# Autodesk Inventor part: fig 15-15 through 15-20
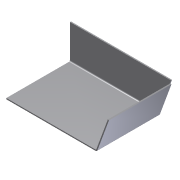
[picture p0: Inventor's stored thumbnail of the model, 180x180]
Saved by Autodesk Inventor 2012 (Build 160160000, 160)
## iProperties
Created: 2005-03
Part Number: fig 15-15 through 15-20
Document SubType Name: Sheet Metal
Designer: CADCIM
Manufacturer: Standard
Standards Organization: Custom
Density: 1 g/cm^3
Sheet Metal Rule: Default
Material: Default
Author: CADCIM
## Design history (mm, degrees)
node "Face2"
  sketch "Sketch1" dims "d32" = 0.5 (= BendRadius)
    geometry: L1 (-36, -8.631)-(4.238, -8.631); L2 (4.238, -8.631)-(4.238, 20); L3 (4.238, 20)-(-36, 20); L4 (-36, 20)-(-36, -8.631)
    constraints: 8 end point, 2 parallel, 1 horizontal, 1 perpendicular
node "Flange3"
node "Flange2"
feature "Corner2" dims "d36" = 2 (= CornerReliefSize), "d37" = 0.5 (= BendRadius), "d38" = 0.5 (= Thickness), "d39" = 0, "Thickness" = 0.5
body "Solid1"
face "Plate2" dims "Thickness" = 0.5
sketch "Sketch3" dims "CornerReliefSize" = 2 (= 4 x Thickness)
  geometry: L1 (39.356, 0)-(39.356, 15); L2 (39.356, 15)-(0, 15); 2 other entities
  constraints: 4 end point, 4 other
face "Plate4" dims "d18" = 0.5 (= BendReliefWidth), "d20" = 1 (= MinimumRemnant), "d22" = 15, "d23" = 90 deg, "d24" = 0.5 (= BendRadius), "d32" = 0.5 (= BendRadius), "Thickness" = 0.5, "CornerReliefSize" = 2 (= 4 x Thickness)
bend "Bend2" dims "d18" = 0.5 (= BendReliefWidth), "d19" = 0.25 (= BendReliefDepth), "d20" = 1 (= MinimumRemnant), "d21" = 0.5 (= BendRadius), "d22" = 15, "d23" = 90 deg, "d24" = 0.5 (= BendRadius), "SeamGap" = 0.01, "Thickness" = 0.5
node "FlatPattern"
sketch "Sketch4" dims "d32" = 0.5 (= BendRadius)
  geometry: L1 (28.631, 0)-(28.631, 15); L2 (28.631, 15)-(0, 15); 2 other entities
  constraints: 4 end point, 4 other
face "Plate5" dims "d29" = 0.5 (= BendReliefWidth), "d31" = 1 (= MinimumRemnant), "d32" = 0.5 (= BendRadius), "d33" = 15, "d34" = 70 deg, "d35" = 0.5 (= BendRadius), "Thickness" = 0.5
bend "Bend3" dims "d29" = 0.5 (= BendReliefWidth), "d30" = 0.25 (= BendReliefDepth), "d31" = 1 (= MinimumRemnant), "d32" = 0.5 (= BendRadius), "d33" = 15, "d34" = 70 deg, "d35" = 0.5 (= BendRadius), "SeamGap" = 0.01, "Thickness" = 0.5
feature "FlatPatternExtrusion2" dims "d0" = 0.5 (derived)
other parameters: "BendRadius" = 0.5 (= Thickness), "BendReliefWidth" = 0.5 (= Thickness), "BendReliefDepth" = 0.25 (= 0.5 x Thickness), "MinimumRemnant" = 1 (= 2 x Thickness), "TransitionRadius" = 0.5 (= BendRadius), "d0" = 0.5 (= BendRadius), "d10" = 0.5 (= BendRadius), "JacobiRadiusSize" = 0.5 (= Thickness), "GapSize" = 0.5 (= Thickness)
